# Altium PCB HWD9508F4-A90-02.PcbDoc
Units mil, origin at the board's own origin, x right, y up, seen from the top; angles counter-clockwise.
Board outline 3307.09 x 2401.57 mil, 2 copper layers (Top Layer, Bottom Layer); 56 components, 97 nets, 444 pads, 231 vias.
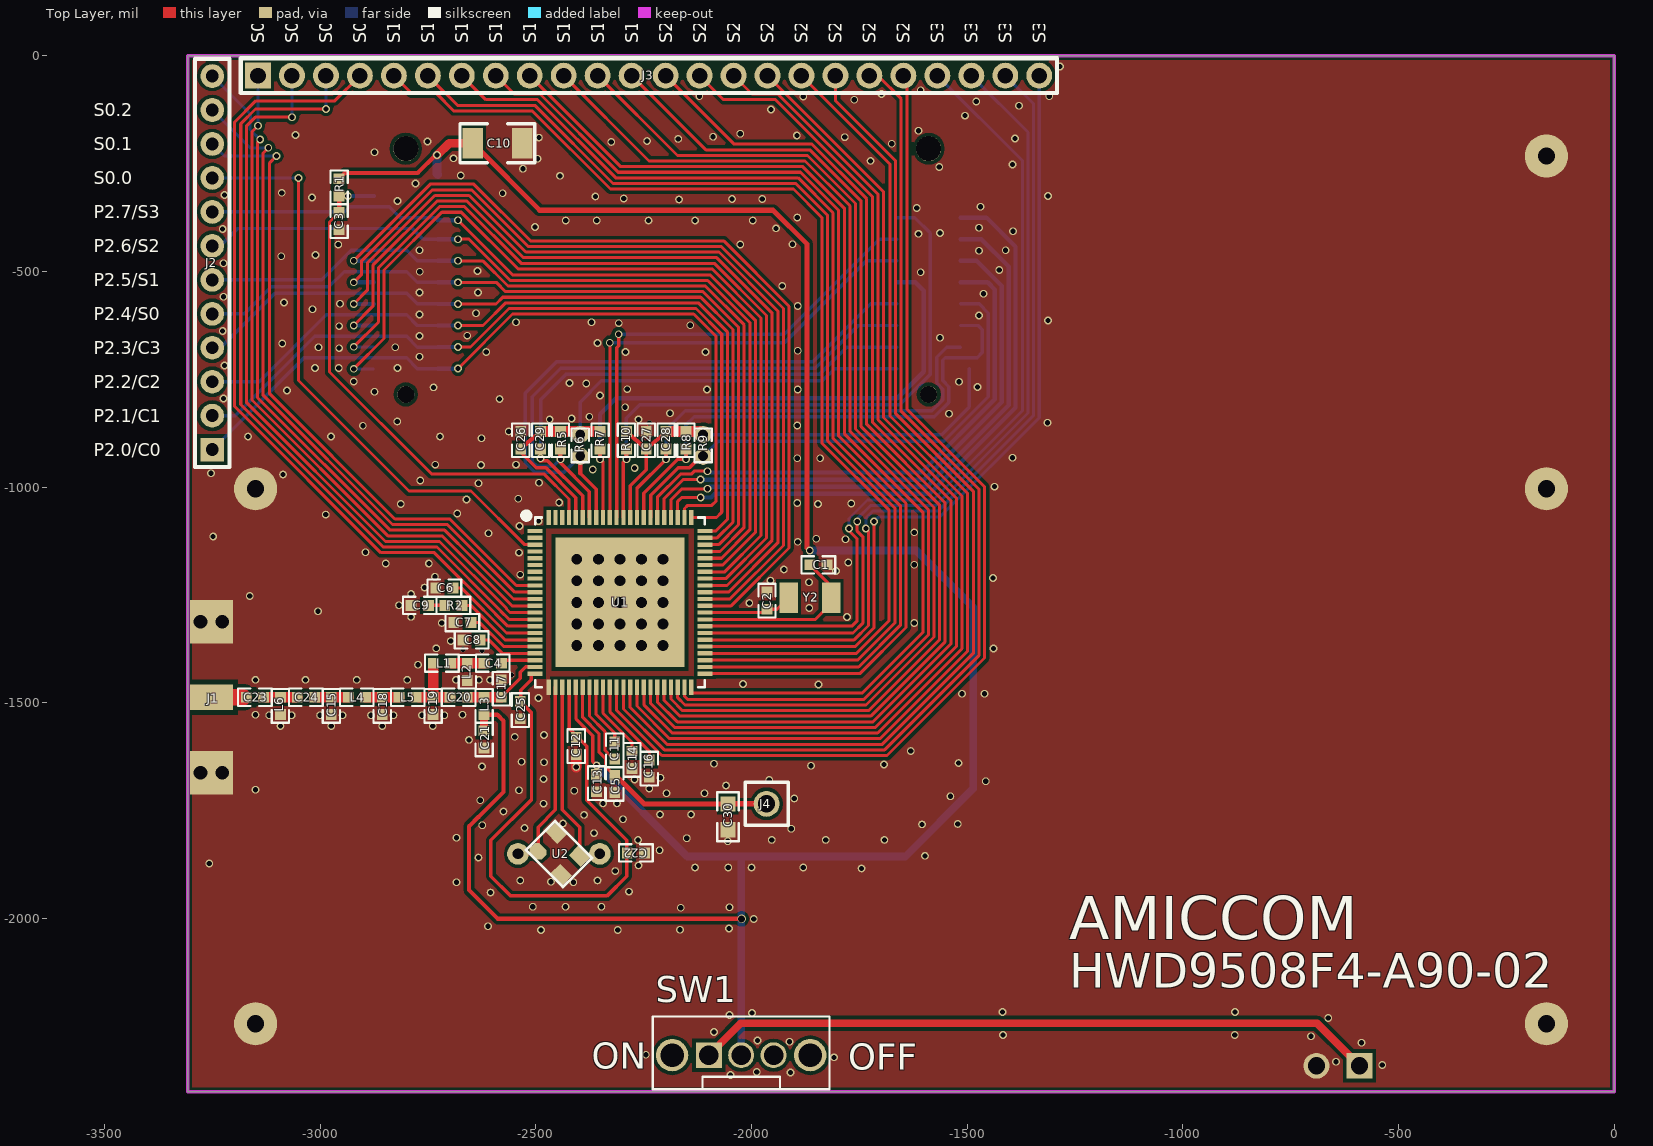
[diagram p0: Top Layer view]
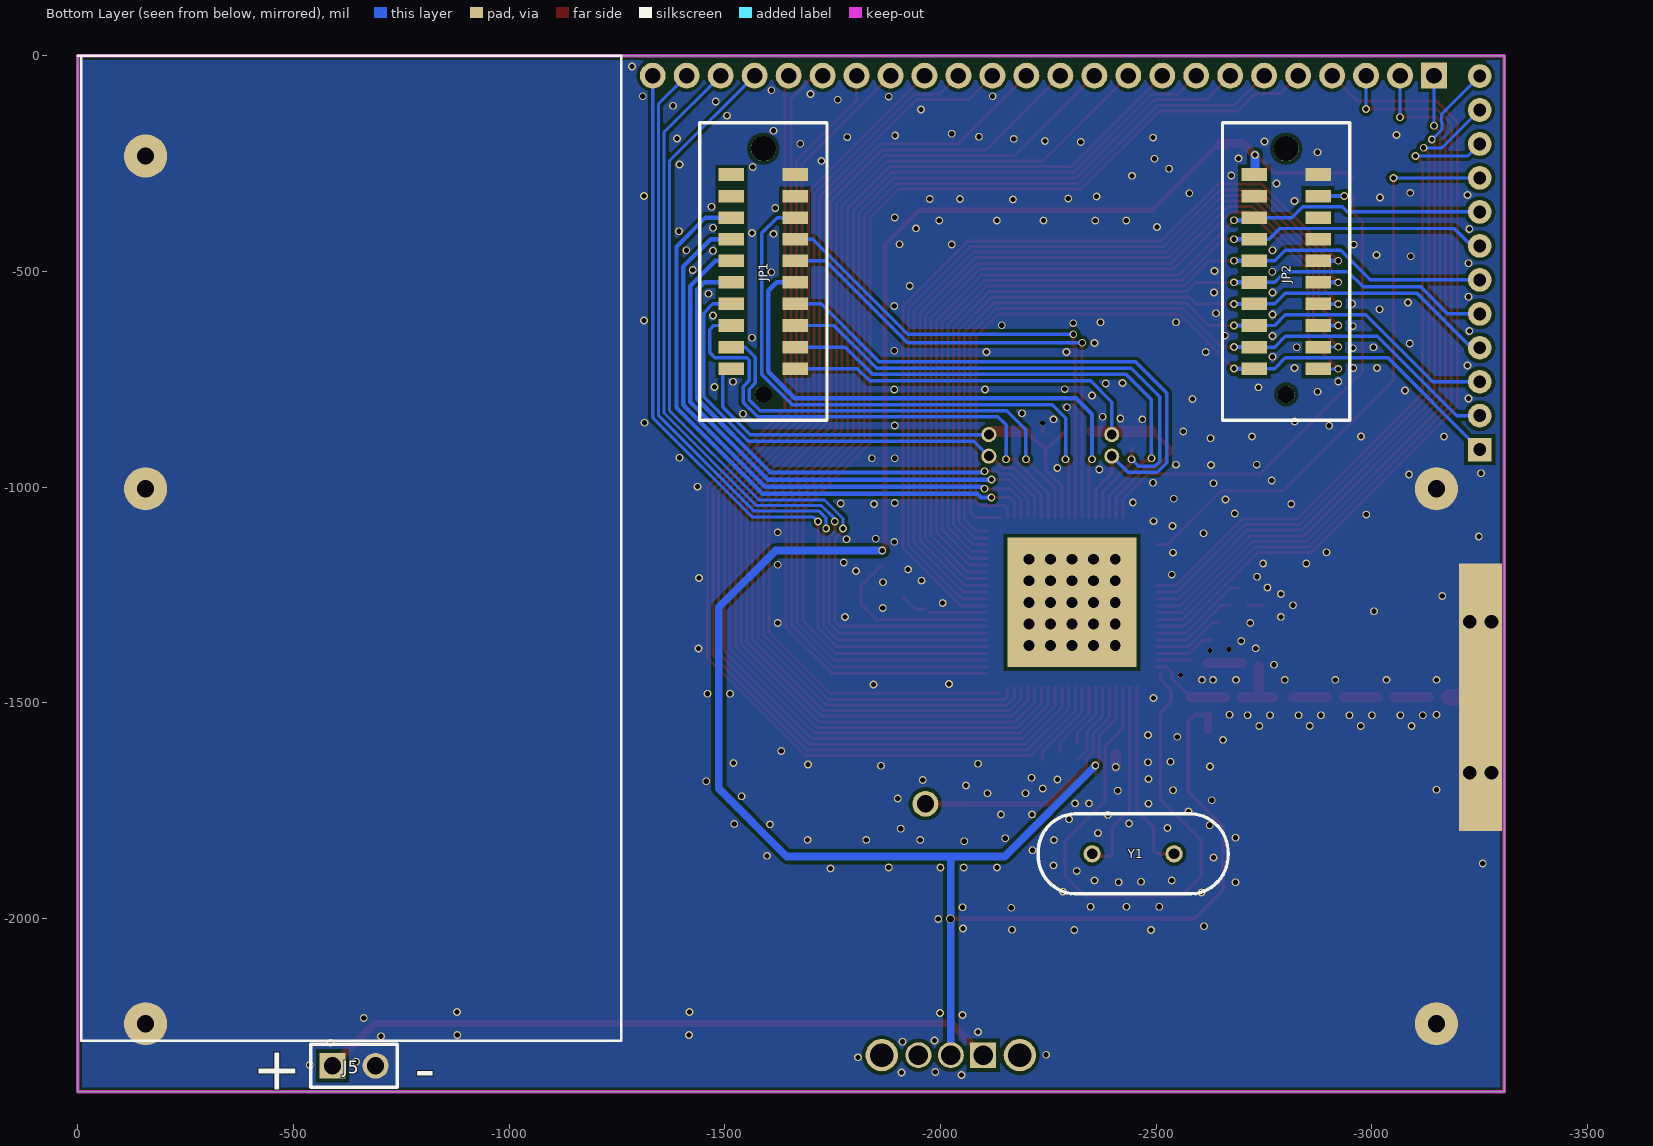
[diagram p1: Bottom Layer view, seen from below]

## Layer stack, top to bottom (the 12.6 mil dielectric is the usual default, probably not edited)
Top Solder: solder mask 0.4, Solder Resist, Dk 3.5
Top Layer: signal copper 1.4
Dielectric1: dielectric 12.6, FR-4, Dk 4.8
Bottom Layer: signal copper 1.4
Bottom Solder: solder mask 0.4, Solder Resist, Dk 3.5

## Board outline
-3307.09,-2401.57 -3307.09,0 0,0 0,-2401.57

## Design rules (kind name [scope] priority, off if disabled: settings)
Clearance Clearance_1 [All vs InNet('TRX')] p1: gap=12
Clearance [(InPoly) vs (IsWire) Or (IsPad) Or (IsVia) Or (IsFill) Or (InPoly)] p2: gap=8
Clearance Clearance_2 [All] p3: gap=6
ComponentClearance [All] p1 off: gap=10 collisioncheckmode=3 verticalgap=10 showdistances=FALSE
FabricationTestPointUsage TestPointUsage [All] p1: valid=0 allowmultiple=FALSE
FabricationTestpoint Testpoint [All] p1: side=3 testpointundercomponent=TRUE minsize=40 maxsize=100 preferedsize=60 minholesize=20 maxholesize=40 preferedholesize=32 testpointgrid=1 allowsidetop=TRUE allowsidebottom=TRUE usegrid=TRUE gridtolerance=0.01
HoleSize [All] p1: absolutevalues=TRUE maxlimit=200 minlimit=1 maxpercent=80.000 minpercent=20.000
PolygonConnect [All] p1: connectstyle=Direct reliefconductorwidth=10 reliefentries=4 polygonreliefangle="90 Angle" airgapwidth=10
RoutingLayers RoutingLayers_1 [InNet('RFIO')] p1: top layer_v5=TRUE bottom layer_v5=TRUE
RoutingLayers [All] p2: top layer_v5=TRUE bottom layer_v5=TRUE
RoutingVias [All] p1: holewidth=12 width=20 viastyle="Through Hole" minholewidth=12 minwidth=10 maxholewidth=16 maxwidth=20
ShortCircuit [All vs InNet('NetL2_1')] p1 off: allowed=FALSE
SolderMaskExpansion [HasPad('*A')] p1: expansion=-30
Width [All] p1: maxlimit=50 minlimit=7 preferedwidth=12
24 further rules are at their usual default settings.

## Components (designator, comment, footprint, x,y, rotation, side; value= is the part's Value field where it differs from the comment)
C1 "22p" 0402#1 -1865.09,-1180.24 r0 top
C2 "22p" 0402#1 -1964.09,-1283.24 r90 top
C3 "22nF" 0402#1 -2956.09,-363.43 r270 top
C4 "100pF" 0402#1 -2579.87,-1408.22 r180 top
C5 "2.2uF" 0402#1 -2317.09,-1668.24 r270 top
C6 "0.1uF" 0402#1 -2692.09,-1234.24 r180 top
C7 "1nF" 0402#1 -2650.09,-1314.24 r180 top
C8 "0.1uF" 0402#1 -2628.87,-1354.24 r180 top
C9 "0.1uF" 0402#1 -2749.09,-1274.24 r180 top
C10 "10uF" 1206 -2589,-203 r180 top (schematic designator C30)
C11 "47nF" 0402#1 -2317.09,-1630.44 r90 top
C12 "0.1uF" 0402#1 -2406.27,-1620.24 r90 top
C13 "2.2uF" 0402#1 -2359.09,-1666.24 r270 top
C14 "1uF" 0402#1 -2277.09,-1612.44 r270 top
C15 "4.7pF" 0402#1 -2974.09,-1527.24 r90 top
C16 "1uF" 0402#1 -2237.09,-1632.44 r270 top
C17 "NC" 0402#1 -2580.09,-1487.47 r90 top
C18 "4.7pF" 0402#1 -2856.09,-1527.24 r90 top
C19 "NC" 0402#1 -2738.09,-1487.24 r270 top
C20 "15pF" 0402#1 -2659.09,-1487.24 r180 top
C21 "2.2uF" 0402#1 -2620,-1565 r270 top
C22 "NC" 0402#1 -2248,-1848 r180 top
C23 "2.2pF" 0402#1 -3131.09,-1487.24 r180 top
C24 "2.2pF" 0402#1 -3013.09,-1487.24 r180 top
C25 "0.1uF" 0402#1 -2536,-1497 r270 top
C26 "820pF" 0402#1 -2535.09,-871.44 r270 top
C27 "NC" 0402#1 -2244.09,-871.44 r270 top
C28 "NC" 0402#1 -2198.09,-871.44 r270 top
C29 "820pF" 0402#1 -2489.09,-871.44 r270 top
C30 "NC" 0603 -2054.95,-1734.44 r270 top (schematic designator C31)
J1 "TRX" "SMA CONNECTOR" -3252.09,-1487.24 r90 top
J2 "CON/12P 2.0" HDR12_2.0 -3250.09,-913.31 r90 top
J3 "CON/24P 2.0" HDR24_2.0 -3144.09,-46.31 r0 top
J4 "LCDCAP_R33" HDR1_2.54 -1965.09,-1734.24 r0 top
J5 "BAT" HDR2_2.54 -590.55,-2341.58 r180 bottom
JP1 "HEADER 10X2B" YAB-V45P-2X#1 -1589.4,-785.27 r90 bottom locked
JP2 "HEADER 10X2B" YAB-V45P-2X#2 -2801.4,-785.27 r90 bottom locked
L1 "1.8pF" 0402#1 -2737.87,-1408.22 r0 top
L2 "8.2nH" 0402#1 -2658.87,-1408.22 r270 top
L3 "18nH" 0402#1 -2620.09,-1527.47 r90 top
L4 "7.5nH" 0402#1 -2935.09,-1487.24 r0 top
L5 "0R" 0402#1 -2817.09,-1487.24 r0 top
L6 "10nH" 0402#1 -3092.09,-1527.24 r90 top
R1 "100K" 0402#1 -2956.09,-285.43 r270 top
R2 "10R" 0402#1 -2711.09,-1274.24 r0 top
R5 "10K" 0402#1 -2443.09,-871.44 r270 top
R6 "thermistor,TSR" 0402#2 -2397.09,-883.44 r270 top
R7 "NC" 0402#1 -2351.09,-871.44 r270 top
R8 "NC" 0402#1 -2152.09,-871.44 r270 top
R9 "NC(thermistor,TSR)" 0402#2 -2112.09,-883.44 r270 top (schematic designator R6)
R10 "NC" 0402#1 -2290.09,-871.44 r270 top
SW1 "SW DIP-3P-180" SW3-2 -2099,-2317 r180 top
U1 "A9508F4_U01 PKG" "QFN 10*10 88L" -2304.95,-1267.36 r0 top
U2 "NC (12.8MHz, CL=20pF)" XTAL_3.2*2.5 -2446.68,-1850.24 r45 top locked
Y1 "12.8MHz, CL=20pF" XTAL1 -2446.66,-1850.22 r180 bottom
Y2 "32.768KHz" XTAL-XB -1904.09,-1256.24 r270 top

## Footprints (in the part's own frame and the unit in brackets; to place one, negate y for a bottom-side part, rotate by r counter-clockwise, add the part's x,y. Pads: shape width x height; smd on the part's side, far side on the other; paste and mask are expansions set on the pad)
0402#1 [mil]
  rect 25x25 smd: 1(0,0) 2(40,0)
  silkscreen extent -19,-20 59,20
0402#2 [mil]
  round 40 / inner round 35 / far side round 35 hole 23: 1(-5,0) 2(45,0)
  silkscreen extent -19,-20 59,20
0603 [mil]
  rect 35x35 smd: 1(0,0) 2(60,0)
  silkscreen extent -27,-25 87,25
1206 [mm]
  rect 1.2x1.8 smd: 1(1.45,0) 2(-1.45,0)
  silkscreen extent -2.21,-1.14 2.21,1.14
HDR1_2.54 [mil]
  round 60 hole 40: 1(0,0)
  silkscreen extent -50,-50 50,50
HDR2_2.54 [mil]
  rect 60x60 hole 40: 1(0,0)
  round 60 hole 40: 2(100,0)
  silkscreen extent -50,-50 150,50
HDR12_2.0 [mil]
  rect 55x55 hole 30: 1(0,0)
  round 55 hole 30: 2(78.74,0) 3(157.48,0) 4(236.22,0) 5(314.96,0) 6(393.7,0) 7(472.44,0) 8(551.18,0) 9(629.92,0) 10(708.66,0) 11(787.4,0) 12(866.14,0)
  silkscreen extent -40,-40 906,40
HDR24_2.0 [mil]
  rect 60x60 hole 36: 1(0,0)
  round 60 hole 36: 2(78.74,0) 3(157.48,0) 4(236.22,0) 5(314.96,0) 6(393.7,0) 7(472.44,0) 8(551.18,0) 9(629.92,0) 10(708.66,0) 11(787.4,0) 12(866.14,0) 13(944.88,0) 14(1023.62,0) 15(1102.36,0) 16(1181.1,0) 17(1259.84,0) 18(1338.58,0) 19(1417.32,0) 20(1496.06,0) 21(1574.8,0) 22(1653.54,0) 23(1732.28,0) 24(1811.02,0)
  silkscreen extent -40,-40 1852,40
"QFN 10*10 88L" [mm]
  rect 0.9x0.25 smd: 1(-5,4.2) 2(-5,3.8) 3(-5,3.4) 4(-5,3) 5(-5,2.6) 6(-5,2.2) 7(-5,1.8) 8(-5,1.4) 9(-5,1) 10(-5,0.6) 11(-5,0.2) 12(-5,-0.2) 13(-5,-0.6) 14(-5,-1) 15(-5,-1.4) 16(-5,-1.8) 17(-5,-2.2) 18(-5,-2.6) 19(-5,-3) 20(-5,-3.4) 21(-5,-3.8) 22(-5,-4.2) 45(5,-4.2) 46(5,-3.8) 47(5,-3.4) 48(5,-3) 49(5,-2.6) 50(5,-2.2) 51(5,-1.8) 52(5,-1.4) 53(5,-1) 54(5,-0.6) 55(5,-0.2) 56(5,0.2) 57(5,0.6) 58(5,1) 59(5,1.4) 60(5,1.8) 61(5,2.2) 62(5,2.6) 63(5,3) 64(5,3.4) 65(5,3.8) 66(5,4.2)
  rect 0.25x0.9 smd: 23(-4.2,-5) 24(-3.8,-5) 25(-3.4,-5) 26(-3,-5) 27(-2.6,-5) 28(-2.2,-5) 29(-1.8,-5) 30(-1.4,-5) 31(-1,-5) 32(-0.6,-5) 33(-0.2,-5) 34(0.2,-5) 35(0.6,-5) 36(1,-5) 37(1.4,-5) 38(1.8,-5) 39(2.2,-5) 40(2.6,-5) 41(3,-5) 42(3.4,-5) 43(3.8,-5) 44(4.2,-5) 67(4.2,5) 68(3.8,5) 69(3.4,5) 70(3,5) 71(2.6,5) 72(2.2,5) 73(1.8,5) 74(1.4,5) 75(1,5) 76(0.6,5) 77(0.2,5) 78(-0.2,5) 79(-0.6,5) 80(-1,5) 81(-1.4,5) 82(-1.8,5) 83(-2.2,5) 84(-2.6,5) 85(-3,5) 86(-3.4,5) 87(-3.8,5) 88(-4.2,5)
  round 0.635 hole 0.635: ""(-2.54,-2.54) ""(-2.54,-1.27) ""(-2.54,0) ""(-2.54,1.27) ""(-2.54,2.54) ""(-1.27,-2.54) ""(-1.27,-1.27) ""(-1.27,0) ""(-1.27,1.27) ""(0,-2.54) ""(0,-1.27) ""(0,1.27) ""(0,2.54) ""(1.27,-2.54) ""(1.27,-1.27) ""(1.27,0) ""(1.27,1.27) ""(1.27,2.54) ""(2.54,-2.54) ""(2.54,-1.27) ""(2.54,0) ""(2.54,1.27) ""(2.54,2.54)
  round 0.762 hole 0.635: ""(-1.27,2.54)
  rect 7.62x7.62 hole 0.635: ""(0,0)
  silkscreen extent -5.62,-5 5,5.21
"SMA CONNECTOR" [mil]
  rect 100x50 hole 32: 0(-175,-25) 0(-175,25) 0(175,-25) 0(175,25)
  rect 620x100 smd far side: 0(0,0)
  rect 59.05x100 smd: 1(0,0)
SW3-2 [mil]
  rect 60x60 hole 45: 1(0,0)
  round 60 hole 45: 2(-75,0) 3(-150,0)
  round 75 hole 55: ""(-235,0) ""(85,0)
  silkscreen extent -280,-90 130,79
XTAL1 [mil]
  round 40 / inner round 40 / far side round 50 hole 25: 1(-95,0) 2(95,0)
  silkscreen extent -220,-93 220,93
XTAL-XB [mm]
  rect 1.8x1.1 smd: 1(0,-0.25) 2(0,2.25)
XTAL_3.2*2.5 [mm]
  oct 0.8x1 smd: 1(-0.76,0.97)
  rect 0.8x1 smd: 2(-0.76,-0.97) 3(0.76,-0.97) 4(0.75,0.97)
  silkscreen extent -1.21,-1.55 1.22,1.53
YAB-V45P-2X#1 [mm]
  rect 0.74x1.5 smd: 1(1.52,1.875) 2(2.79,1.875) 3(4.06,1.875) 4(5.33,1.875) 5(6.6,1.875) 6(7.87,1.875) 7(9.14,1.875) 8(10.41,1.875) 9(11.68,1.875) 10(12.95,1.875) 11(1.52,-1.875) 12(2.79,-1.875) 13(4.06,-1.875) 14(5.33,-1.875) 15(6.6,-1.875) 16(7.87,-1.875) 17(9.14,-1.875) 18(10.41,-1.875) 19(11.68,-1.875) 20(12.95,-1.875)
  round 1 hole 1 unplated: ""(0,0)
  round 1.473 hole 1.473 unplated: ""(14.47,0)
  silkscreen extent -1.52,-3.75 15.98,3.75
YAB-V45P-2X#2 [mm]
  rect 0.74x1.5 smd: 1(1.52,1.875) 2(2.79,1.875) 3(4.06,1.875) 4(5.33,1.875) 6(7.87,1.875) 7(9.14,1.875) 8(10.41,1.875) 9(11.68,1.875) 10(12.95,1.875) 11(1.52,-1.875) 12(2.79,-1.875) 13(4.06,-1.875) 14(5.33,-1.875) 15(6.6,-1.875) 16(7.87,-1.875) 17(9.14,-1.875) 18(10.41,-1.875) 19(11.68,-1.875) 20(12.95,-1.875)
  rect 0.76x1.5 smd: 5(6.6,1.875)
  round 1 hole 1 unplated: ""(0,0)
  round 1.473 hole 1.473 unplated: ""(14.47,0)
  silkscreen extent -1.52,-3.75 15.98,3.75

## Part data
C1 C2 C11: library part C/0603, "Chip C"
C3 C26 C27 C28 C29: library part C/0402, "Chip C"
C4 C5 C6 C7 C8 C9 C10 C12 C13 C14 C15 C16 C17 C18 C19 C20 C21 C22 C23 C24 C25 C30: library part CAP
J1: library part "SMA CONNECTOR"
J2 J3: "Hole 36mil"
J4: library part "CON/1P 2.54", "Hole 40mil"
J5: library part "CON/2P 2.54", "Hole 40mil"
JP1 JP2: "Pitch 2.54mm"
L1 L2 L3 L4 L5 L6: library part L/0402, "Chip L"
R1: library part R/0603, "Chip  R"
R2: library part RES1
R5 R6 R7 R8 R9 R10: library part R/0402, "Chip R"
U1: library part A9508F4
U2: library part CRYSTAL/5*3.2
Y1 Y2: library part CRYSTAL, "Crystal"

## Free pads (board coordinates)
  round 18 hole 12: A(-3167.09,-882.87) A(-3150.09,-1527.87) A(-3150.09,-1446.87) A(-3118.09,-1528.87) A(-3092.09,-1553.87) A(-3086.09,-970.87) A(-3066.09,-1528.87) A(-3034.09,-1446.87) A(-3005,-1288) A(-3000.09,-1528.87) A(-2987.09,-1063.87) A(-2974.09,-1553.87) A(-2958,-438) A(-2948.09,-1528.87) A(-2915.09,-1446.87) A(-2895,-1151) A(-2882.09,-1528.87) A(-2874.09,-779.24) A(-2856.09,-1553.87) A(-2830.09,-1528.87) A(-2821.09,-847.87) A(-2817.09,-1273.87) A(-2798.09,-1446.87) A(-2789.09,-1300.87) A(-2789.09,-1247.87) A(-2773.09,-1411.87) A(-2764.09,-1528.87) A(-2758.09,-1232.87) A(-2739.09,-1553.87) A(-2737.09,-768.87) A(-2734.09,-1207.87) A(-2731.09,-1373.87) A(-2722.09,-882.87) A(-2718.09,-1314.87) A(-2712.09,-1528.87) A(-2697.09,-1356.87) A(-2685.09,-1446.87) A(-2670.09,-1527.87) A(-2655,-1586) A(-2633.09,-1858.87) A(-2632.09,-1446.87) A(-2626.09,-886.87) A(-2624.09,-1783.87) A(-2615,-687) A(-2606.09,-1446.87) A(-2605.09,-1939.87) A(-2584.09,-795.87) A(-2575.09,-1751.87) A(-2562.8,-871.07) A(-2546,-618) A(-2539.09,-1702.87) A(-2536.24,-1911.87) A(-2533.09,-1636.87) A(-2530.09,-262.24) A(-2526.09,-1790.24) A(-2507.09,-1972.87) A(-2496,-239) A(-2493,-190) A(-2482.09,-1733.87) A(-2482.09,-1676.87) A(-2481,-1638) A(-2465.09,-1914.87) A(-2437.09,-1779.87) A(-2431.09,-1972.87) A(-2430.8,-382.24) A(-2413.09,-1915.87) A(-2411.09,-1703.87) A(-2406.27,-1648.87) A(-2388.09,-1759.87) A(-2371,-618) A(-2365.09,-1802.24) A(-2362.09,-326.24) A(-2358.8,-382.24) A(-2357.09,-1911.87) A(-2348.09,-1972.87) A(-2344.09,-1733.24) A(-2325.09,-199.87) A(-2316.09,-1890.24) A(-2312.09,-1733.24) A(-2298.09,-1769.87) A(-2296.09,-331.24) A(-2284.09,-1937.87) A(-2271.09,-1677.87) A(-2263,-1818) A(-2262,-1877) A(-2242.09,-197.87) A(-2238.8,-382.24) A(-2237.09,-1698.87) A(-2213.09,-1841.87) A(-2212.09,-1758.87) A(-2211.09,-1673.87) A(-2197.09,-1709.87) A(-2170.09,-192.87) A(-2168.09,-333.24) A(-2150.09,-1813.87) A(-2140.09,-1758.87) A(-2131,-1882) A(-2130.8,-382.24) A(-2109.09,-1709.87) A(-2089.09,-187.87) A(-2087.09,-1641.36) A(-2059.09,-1691.87) A(-2055.09,-1820.87) A(-2054,-1882) A(-2045.09,-332.24) A(-2026.09,-180.87) A(-2005.09,-1268.87) A(-2000,-1882) A(-1997.09,-382.24) A(-1975.09,-332.24) A(-1959.09,-1678.87) A(-1956.09,-1216.87) A(-1953.09,-1817.87) A(-1943.09,-400.24) A(-1925.09,-1190.87) A(-1908.09,-1791.87) A(-1905.09,-437.29) A(-1901.09,-1721.87) A(-1894.09,-375.24) A(-1862.09,-1645.87) A(-1828.09,-1817.87) A(-1784.09,-188.87) A(-1745,-1884) A(-1724.09,-243.87) A(-1692.09,-1817.87) A(-1631,-1612) A(-1604.8,-1781.87) A(-1598.09,-1854.87) A(-1539.09,-1716.87) A(-1522.09,-1780.87) A(-1520.09,-1639.87) A(-1457.09,-1681.87)
  round 12 hole 12: A(-2669.09,-1375.87) A(-2625.09,-1378.87) A(-2556.09,-1435.87) A(-2237.09,-851.44)
  round 100 hole 40: ""(-3149.61,-2244.09) ""(-3149.61,-1003.94) ""(-157.48,-2244.09) ""(-157.48,-1003.94) ""(-157.48,-232.61)

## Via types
v1: diameter 18, hole 12, Top Layer to Bottom Layer, 204 vias
v2: diameter 18, hole 12, Top Layer to Bottom Layer, tented both sides, 26 vias
v3: diameter 20, hole 16, Top Layer to Bottom Layer, 1 vias

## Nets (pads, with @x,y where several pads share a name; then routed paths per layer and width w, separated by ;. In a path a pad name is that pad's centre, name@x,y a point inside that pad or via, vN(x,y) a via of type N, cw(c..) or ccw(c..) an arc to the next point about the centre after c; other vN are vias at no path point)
BPBG: C7.1 U1.18 | length 164.3
  Top Layer w7: C7.1@-2643.09,-1314.24 -2630.09,-1314.24 -2574.61,-1369.72 U1.18
CPO: C16.1 U1.32 | length 206.1
  Top Layer w7: U1.32 -2328.57,-1520.76 -2237.09,-1612.24 C16.1
GND: C1.2 C2.2 C3.2 C5.2 C6.2 C7.2 C8.2 C9.2 C10.2 C12.1 C13.2 C14.2 C15.1 C16.2 C17.2 C18.1 C19.2 C21.2 C22.1 C25.2 C26.1 C27.1 C30.2 J1.0 J5.2 JP1.20 JP2.20 L2.2 L6.1 pad. pad.A U1.23 U2.2 U2.4 | length 48.6
  Top Layer w10: C27.1@-2237.09,-871.44 pad.A@-2237.09,-851.44
  Top Layer w25: pad.A@-2406.27,-1648.87 C12.1
  other v1: -2049,-2363 -1910,-2357 -1988,-2356 -538,-2340 -645,-2332 -1809,-2322 -2245,-2316 -586,-2288 -1912,-2286 -1986,-2283 -703,-2273 -1417,-2270 -880,-2270 -2087,-2263 -663,-2231 -2051,-2224 -1999,-2219 -1418,-2217 -879,-2217 -2488,-2027 -2310,-2027 -2166,-2026 -2052,-2023 -2611,-2018 -1995,-2001 -2164,-1975 -2051,-1974 -2684,-1916 -1880,-1882 -3257.09,-1872.58 -2684,-1813 -2629,-1726 -3150.09,-1701.58 -2625,-1648 -1693,-1643 -2549,-1579 -2481,-1575 -2494,-1489 -1512,-1479 -1460,-1479 -1845.09,-1457.58 -2020.09,-1456.58 -1439,-1374 -1623,-1315 -1779,-1301 -1866.09,-1280.58 -3163.09,-1252.58 -1867.09,-1220.58 -1440,-1211 -2536,-1203 -1804.09,-1194.58 -1623,-1180 -2848,-1177 -2748,-1177 -1776,-1175 -2539,-1152 -1893,-1127 -1782,-1121 -1850,-1120 -3248.09,-1114.58 -2610,-1107 -1623,-1105 -2538,-1090 -2494,-1079 -2682,-1061 -2813,-1039 -1846,-1039 -1769,-1038 -1894,-1037 -2446,-1036 -2661,-1029 -2541,-1027 -1437,-999 -2633,-991 -2493,-990 -2768,-985 -3253,-968 -2368,-959 -2271,-956 -2627,-949 -2733,-948 -2546,-948 -1894,-933 -1841,-933 -1395,-932 -2975,-883 -2901,-858 -1894,-857 -1314,-851 -2468,-843 -2262,-843 -2417,-841 -2376,-837 -1542,-830 -2189,-829 -2293,-815 -3224,-795 -2351,-788 -3077,-776 -2103,-774 -1893,-774 -2288,-773 -1476,-768 -2383,-760 -2422,-759 -1519,-756 -2922,-755 -3012,-724 -2957,-724 -2821,-724 -3222,-718 -2770,-698 -2292,-687 -2107,-687 -1893,-684 -2956,-678 -3004,-676 -2826,-676 -3088,-667 -2357,-666 -1563,-654 -2770,-650 -2659,-649 -3226,-638 -2956,-627 -2142,-625 -2308,-620 -1313,-614 -1473,-602 -2770,-600 -2639,-597 -3018,-588 -1893,-580 -2954,-575 -3084,-572 -3224,-559 -1462,-552 -2770,-549 -2634,-549 -1929,-534 -1608,-502 -2769,-501 -2635,-499 -1426,-497 -3224,-481 -3090,-465 -3011,-462 -1473,-452 -2770,-451 -1411,-451 -2026,-438 -1613,-413 -1563,-411 -1394,-407 -3226,-402 -1473,-399 -2502,-397 -1617,-353 -1469,-350 -2821,-337 -3019,-329 -1313,-325 -3222,-323 -2577,-319 -3089,-318 -2779,-296 -2674,-278 -2444.09,-278.58 -1565,-258 -1395,-252 -2691,-238 -2874,-224 -1675,-204 -2751,-199 -1389,-192 -1895,-185 -3057,-184 -1613,-174 -1505,-139 -1955,-125 -1380,-116 -1479,-106 -1762,-102 -1880,-95 -2121,-94 -1310,-94 -1699,-89 -1608,-80 -1285,-25
LCDCAP_R33: C5.1 C30.1 J4.1 U1.28 | length 614.6
  Top Layer w7: U1.28 -2391.56,-1533.77 -2354.09,-1571.24 -2354.09,-1613.87 -2339.09,-1628.87 -2339.09,-1646.87 C5.1@-2314.09,-1671.87 ; C5.1@-2314.09,-1672.24 C5.1@-2311.09,-1672.24
  Top Layer w12: C5.1@-2311.09,-1672.24 -2248.89,-1734.44 C30.1 -2054.75,-1734.24 J4.1
NetC4_2: C4.2 L1.2 L2.1 | length 78
  Top Layer w25: L1.2 L2.1 C4.2
NetC9_1: C9.1 R2.1 | length 38
  Top Layer w8: C9.1 R2.1
NetC11_1: C11.1 U1.29 | length 192.6
  Top Layer w7: U1.29 -2375.81,-1530.52 -2340.09,-1566.24 -2340.09,-1609.44 C11.1@-2317.09,-1632.44
NetC11_2: C11.2 U1.30 | length 146
  Top Layer w7: U1.30 -2360.06,-1527.27 -2317.09,-1570.24 C11.2@-2317.09,-1592.44
NetC15_2: C15.2 C24.1 L4.1 | length 78
  Top Layer w25: C24.1 C15.2 L4.1
NetC18_2: C18.2 L4.2 L5.1 | length 78
  Top Layer w25: L4.2 C18.2 L5.1
NetC19_1: C19.1 C20.2 L1.1 L5.2 | length 134.2
  Top Layer w25: L5.2@-2770.09,-1487.22 -2731.09,-1487.22 C20.2 ; C19.1@-2737.87,-1480.44 L1.1@-2737.87,-1417.24
NetC23_1: C23.1 C24.2 L6.2 | length 78
  Top Layer w25: C23.1 L6.2 C24.2
NetJ5_1: J5.1 SW1.1 | length 1579.9
  Top Layer w18: SW1.1 -2025,-2243 -689.13,-2243 J5.1
P0.0: C26.2 C29.1 JP1.11 R5.1 R6.1 R7.1 U1.84 | length 1267.7
  Top Layer w8: C26.2 -2535.09,-919.44 -2499.28,-955.24 -2476.55,-955.24 -2407.31,-1024.49 U1.84
  Top Layer w10: C26.2 C29.1 C29.1@-2491.09,-871.44
  Top Layer w25: C29.1 R5.1 -2397.09,-871.44 R7.1
  Bottom Layer w8: R6.1 -2397.09,-803.09 -2348,-754 -1836,-754 -1807.43,-725.43 JP1.11
P0.1: C29.2 JP1.12 U1.83 | length 1221.1
  Top Layer w8: v1@-2489.09,-939 -2473,-939 -2391.56,-1020.44 U1.83
  Top Layer w10: v1@-2489.09,-939 C29.2
  Bottom Layer w8: v1(-2489.09,-933) -2489.09,-797.09 -2431,-739 -1843,-739 -1779.43,-675.43 JP1.12
P0.2: JP1.13 R5.2 U1.82 | length 1326.9
  Top Layer w8: v1(-2443.09,-935.44) -2443.09,-943.13 -2375.81,-1010.4 U1.82
  Top Layer w10: v1(-2443.09,-935.44) R5.2
  Bottom Layer w8: v1(-2443.09,-935.44) -2459.65,-952 -2496.96,-952 -2508.09,-940.87 -2508.09,-790.61 -2442.47,-725 -1852,-725 -1752.43,-625.43 JP1.13
P0.3: JP1.14 R6.2 U1.81 | length 1419.2
  Top Layer w8: -2397.09,-967.91 -2360.06,-1004.94 U1.81
  Top Layer w10: -2397.09,-967.91 R6.2
  Bottom Layer w8: R6.2 -2434.65,-966 -2502.76,-966 -2525,-943.76 -2525,-782 -2453,-710 -1858,-710 -1723.43,-575.43 JP1.14
P0.4/DEBUG_EN_EK: JP1.15 R7.2 U1.80 | length 1315.1
  Top Layer w8: v1(-2351.09,-935.44) -2344.32,-942.21 U1.80
  Top Layer w10: v1(-2351.09,-935.44) R7.2
  Bottom Layer w10: v1(-2351.09,-935.44) -2351.09,-831.09 -2314,-794 -1662.21,-794 -1601,-732.79 -1601,-545 -1620.57,-525.43 JP1.15
P0.5: JP1.16 U1.79 | length 1149
  Top Layer w7: U1.79 v2(-2328.57,-665.61)
  Bottom Layer w8: v2(-2328.57,-665.61) -1923.61,-665.61 -1733.43,-475.43 JP1.16
P0.6: JP1.17 U1.78 | length 1162.9
  Top Layer w8: U1.78 -2312.82,-676.74 -2308.09,-672 v2(-2308.09,-645.61)
  Bottom Layer w8: v2(-2308.09,-645.61) -1924.61,-645.61 -1704.43,-425.43 JP1.17
P0.7/GIO1: JP1.18 R10.2 U1.77 | length 1423.2
  Top Layer w8: U1.77 -2297.07,-942.43 v1(-2290.09,-935.44)
  Top Layer w10: v1(-2290.09,-935.44) R10.2
  Bottom Layer w8: v1(-2290.09,-935.44) -2290.09,-840.09 -2259,-809 -1656,-809 -1586,-739 -1586,-411 -1621.57,-375.43 JP1.18
P1.0: C27.2 C28.1 JP1.1 R8.1 R9.1 R10.1 U1.76 | length 1117.8
  Top Layer w8: U1.76 -2281.32,-997.32 -2244.09,-960.09 C27.2
  Top Layer w10: R10.1@-2289.09,-871.44 R10.1 C27.2 -2197.27,-872.42 C28.1@-2196.09,-871.44
  Top Layer w25: C28.1@-2196.09,-871.44 R8.1 -2119.09,-871.44 R9.1
  Bottom Layer w8: R9.1 -1559.08,-878.44 -1495,-814.36 JP1.1@-1495,-726
P1.1: C28.2 JP1.2 U1.75 | length 1095.2
  Top Layer w8: U1.75 -2265.58,-1002.93 v1(-2198.09,-935.44)
  Top Layer w10: v1(-2198.09,-935.44) C28.2
  Bottom Layer w8: v1(-2198.09,-935.44) -2198.09,-867.09 -2154,-823 -1581.8,-823 -1557,-798.2 -1557,-772.8 -1571,-758.8 -1571,-699 -1547.43,-675.43 JP1.2
P1.2/GIO2: JP1.3 R8.2 U1.74 | length 1231.6
  Top Layer w8: U1.74 -2249.83,-1014.05 -2171.22,-935.44 v1(-2152.09,-935.44)
  Top Layer w10: v1(-2152.09,-935.44) R8.2
  Bottom Layer w8: v1(-2152.09,-935.44) -2152.09,-856.09 -2133,-837 -1576,-837 -1543,-804 -1543,-767 -1557,-753 -1557,-706 -1551,-700 -1477,-700 -1465,-688 -1465,-635 -1474.57,-625.43 JP1.3
P1.3/CKO_EK: JP1.4 R9.2 U1.73 | length 1206
  Top Layer w8: U1.73 -2234.08,-1019.24 -2170.09,-955.24 -2143.89,-955.24 -2124.09,-935.44 R9.2@-2106.09,-935.44
  Top Layer w10: R9.2@-2106.09,-935.44 R9.2@-2106.09,-928.44
  Bottom Layer w8: R9.2 -2077.65,-894 -1554.84,-894 -1451,-790.16 -1451,-597 -1472.57,-575.43 JP1.4
P1.4/TTDIO: JP1.5 U1.72 | length 1266.7
  Top Layer w7: U1.72 -2218.33,-1023.49 -2164.84,-970 -2139.55,-970 -2132.8,-963.24 v2(-2102.09,-963.24)
  Bottom Layer w10: v2(-2102.09,-963.24) -2099.09,-966.24 -1605.87,-966.24 -1436,-796.37 -1436,-542 -1452.57,-525.43 JP1.5
P1.5/TTCLK: JP1.6 U1.71 | length 1308.7
  Top Layer w7: U1.71 -2202.58,-1026.74 -2158.84,-983 -2118.84,-983 v2(-2118.09,-982.24)
  Bottom Layer w10: v2(-2118.09,-982.24) -2117.09,-983.24 -1600.24,-983.24 -1420,-803 -1420,-534 -1478.57,-475.43 JP1.6
P1.6: JP1.7 U1.70 | length 1373.5
  Top Layer w7: U1.70 -2186.84,-1029.38 -2161.46,-1004 v1(-2102,-1004)
  Bottom Layer w10: v1(-2102,-1004) -2097.24,-999.24 -1593.62,-999.24 -1404,-809.63 -1404,-489 -1467.57,-425.43 JP1.7
P1.7: JP1.8 U1.69 | length 1439.2
  Top Layer w7: U1.69 -2171.09,-1033.09 -2162,-1024 v1(-2118,-1024)
  Bottom Layer w10: v1(-2118,-1024) -2093.72,-1024 -2084.96,-1015.24 -1586.99,-1015.24 -1388,-816.25 -1388,-443 -1455.57,-375.43 JP1.8
P2.0/C0: J2.1 JP2.1 U1.68 | length 1823
  Top Layer w7: v2(-2680.54,-725.43) -2554.1,-599 -2134,-599 -2082.09,-650.91 -2082.09,-1032.24 -2093.09,-1043.24 -2149.09,-1043.24 -2155.34,-1049.5 U1.68
  Bottom Layer w8: J2.1 -3037.39,-700.61 -2799.45,-700.61 -2774.63,-725.43 JP2.1
  Bottom Layer w10: JP2.1 v2(-2680.54,-725.43)
P2.1/C1: J2.2 JP2.2 U1.67 | length 1798.5
  Top Layer w7: v2(-2680.54,-675.43) -2651.43,-675.43 -2562,-586 -2128.62,-586 -2069.09,-645.53 -2069.09,-1058.24 -2081.35,-1070.51 U1.67
  Bottom Layer w8: J2.2@-3231.09,-834.58 -3196.58,-834.58 -3012.61,-650.61 -2799.45,-650.61 -2774.63,-675.43 JP2.2
  Bottom Layer w10: JP2.2 v2(-2680.54,-675.43)
P2.2/C2: J2.3 JP2.3 U1.66 | length 1797.3
  Top Layer w7: v2(-2680.54,-625.43) -2622.43,-625.43 -2570,-573 -2123.23,-573 -2056.09,-640.15 -2056.09,-1075.26 -2082.84,-1102.01 U1.66
  Bottom Layer w8: J2.3@-3231.09,-755.84 -3140.83,-755.84 -2985.61,-600.61 -2799.45,-600.61 -2774.63,-625.43 JP2.3
  Bottom Layer w10: JP2.3 v2(-2680.54,-625.43)
P2.3/C3: J2.4 JP2.4 U1.65 | length 1814.6
  Top Layer w7: v2(-2680.54,-575.43) -2592.43,-575.43 -2577,-560 -2117.85,-560 -2043.09,-634.76 -2043.09,-1081.24 -2079.6,-1117.76 U1.65
  Bottom Layer w8: J2.4@-3231.09,-677.09 -3104.61,-550.61 -2799.45,-550.61 -2774.63,-575.43 JP2.4
  Bottom Layer w10: JP2.4 v2(-2680.54,-575.43)
P2.4/S0: J2.5 JP2.5 U1.64 | length 1849.9
  Top Layer w7: v2(-2680.54,-525.43) -2591.69,-525.43 -2570.12,-547 -2112.46,-547 -2030.09,-629.38 -2030.09,-1087.24 -2076.35,-1133.5 U1.64
  Bottom Layer w8: J2.5@-3231.09,-598.35 -3175.35,-598.35 -3113,-536 -2980,-536 -2944.61,-500.61 -2799.45,-500.61 -2774.63,-525.43 JP2.5
  Bottom Layer w10: JP2.5 v2(-2680.54,-525.43)
P2.5/S1: J2.6 JP2.6 U1.63 | length 1897.9
  Top Layer w7: v2(-2680.54,-475.43) -2623.31,-475.43 -2564.74,-534 -2107.08,-534 -2017.09,-623.99 -2017.09,-1093.24 -2073.09,-1149.25 U1.63
  Bottom Layer w8: J2.6@-3231.09,-519.61 -2996.61,-519.61 -2927.61,-450.61 -2799.45,-450.61 -2774.63,-475.43 JP2.6
  Bottom Layer w10: JP2.6 v2(-2680.54,-475.43)
P2.6/S2: J2.7 JP2.7 U1.62 | length 1945.9
  Top Layer w7: v2(-2680.54,-425.43) -2654.92,-425.43 -2559.36,-521 -2101.69,-521 -2004.09,-618.61 -2004.09,-1099.24 -2069.84,-1165 U1.62
  Bottom Layer w8: J2.7@-3231.09,-440.87 -3190.83,-400.61 -2786.39,-400.61 -2761.57,-425.43 JP2.7
  Bottom Layer w10: JP2.7 v2(-2680.54,-425.43)
P2.7/S3: J2.8 JP2.8 U1.61 | length 1991.4
  Top Layer w7: v2(-2680.54,-381.43) -2553.97,-508 -2096.31,-508 -1991.09,-613.22 -1991.09,-1105.24 -2066.59,-1180.75 U1.61
  Bottom Layer w8: J2.8@-3231.09,-362.13 -2943.13,-362.13 -2931.61,-350.61 -2839.39,-350.61 -2814.57,-375.43 JP2.8
  Bottom Layer w10: JP2.8@-2727.58,-381.43 v2(-2680.54,-381.43)
P3.0: JP2.11 U1.60 | length 2004.5
  Top Layer w7: v1(-2922,-726) -2851.77,-655.77 -2851.77,-496.77 -2717.93,-362.93 -2672.87,-362.93 -2541.56,-494.24 -2091.68,-494.24 -1978.09,-607.84 -1978.09,-1112.47 -2062.11,-1196.5 U1.60
  Bottom Layer w7: v1(-2922,-726) JP2.11@-2875.79,-726
P3.1: JP2.12 U1.59 | length 2014.1
  Top Layer w7: v1(-2922,-675) -2864.77,-617.77 -2864.77,-491.38 -2723.32,-349.93 -2665.37,-349.93 -2534.06,-481.24 -2086.29,-481.24 -1965.09,-602.45 -1965.09,-1117.86 -2059.47,-1212.24 U1.59
  Bottom Layer w7: v1(-2922,-675) JP2.12@-2875.65,-675
P3.2: JP2.13 U1.58 | length 2025.7
  Top Layer w7: v2(-2922.27,-625.43) -2877.77,-580.93 -2877.77,-486 -2728.7,-336.93 -2659.99,-336.93 -2528.68,-468.24 -2080.91,-468.24 -1952.09,-597.07 -1952.09,-1123.24 -2056.83,-1227.99 U1.58
  Bottom Layer w10: v2(-2922.27,-625.43) JP2.13
P3.3: JP2.14 U1.57 | length 2036.4
  Top Layer w7: v2(-2922.27,-575.43) -2890.77,-543.93 -2890.77,-480.61 -2734.09,-323.93 -2654.6,-323.93 -2523.29,-455.24 -2075.53,-455.24 -1939.09,-591.68 -1939.09,-1129.24 -2053.58,-1243.74 U1.57
  Bottom Layer w10: v2(-2922.27,-575.43) JP2.14
P3.4: JP2.15 U1.56 | length 2047.1
  Top Layer w7: v2(-2922.27,-525.43) -2903.77,-506.93 -2903.77,-475.23 -2739.47,-310.93 -2649.22,-310.93 -2517.91,-442.24 -2070.14,-442.24 -1926.09,-586.3 -1926.09,-1135.24 -2050.33,-1259.49 U1.56
  Bottom Layer w10: v2(-2922.27,-525.43) JP2.15
P3.5: JP2.16 U1.55 | length 2057.9
  Top Layer w7: v2(-2922.27,-475.43) -2922.27,-475.34 -2744.86,-297.93 -2643.84,-297.93 -2512.53,-429.24 -2064.76,-429.24 -1913.09,-580.91 -1913.09,-1141.24 -2047.08,-1275.24 U1.55
  Bottom Layer w10: v2(-2922.27,-475.43) JP2.16
P3.6: JP2.17
P3.7: JP2.18
REGI: C10.1 C13.1 C21.1 JP2.10 L3.1 R1.1 SW1.2 U1.27 | length 5717.4
  Top Layer w7: U1.27 -2407.31,-1537.02 -2368.09,-1576.24 -2368.09,-1636.43 v2(-2359.09,-1645.43) C13.1
  Top Layer w10: R1.1 -2942.65,-272 -2774,-272 v2@-2731,-229 ; L3.1 -2589.53,-1527.47 -2575,-1542 -2575,-1707 -2631.87,-1763.87 -2632.37,-1763.87 -2655,-1786.5 -2655,-1934 -2588,-2001 v3(-2023,-2001)
  Top Layer w12: C10.1@-2660.17,-212.24 -2636.76,-212.24 -2490.76,-358.24 -1950.09,-358.24 -1871.09,-437.24 -1871.09,-1141.24 v2(-1865.09,-1147.24)
  Top Layer w18: C21.1 L3.1@-2620,-1527.55
  Top Layer w20: v2@-2729,-231 -2701,-203 C10.1
  Bottom Layer w18: v2(-2359.09,-1645.43) -2359.09,-1645.82 -2148.33,-1856.58 -1643.79,-1856.58 -1486.09,-1698.87 -1486.09,-1278.93 -1617.78,-1147.24 v2(-1865.09,-1147.24) ; SW1.2 -2024,-1858.58
  Bottom Layer w20: v2(-2729,-230) -2729,-274.02 JP2.10
REGO: C14.1 U1.31 | length 176.1
  Top Layer w7: U1.31 -2344.32,-1524.01 -2277.09,-1591.24 C14.1
RESETN: C3.1 JP2.19 R1.2 U1.85 | length 1217.5
  Top Layer w7: C3.1 -2978.09,-385.43 -2978.09,-733.22 -2742.06,-969.24 -2481.65,-969.24 -2423.06,-1027.83 U1.85
  Top Layer w10: C3.1 R1.2 v1(-2936,-325.43)
  Bottom Layer w10: v1(-2936,-325.43) JP2.19
RFI: C4.1 U1.20 | length 78.1
  Top Layer w8: C4.1@-2579.87,-1401.22 U1.20
RFO: C17.1 C20.1 L3.2 U1.21 | length 195
  Top Layer w8: C17.1@-2580.31,-1487.24 C17.1 ; C17.1 -2536.09,-1443.47 -2536.09,-1429.24 -2523.81,-1416.97 U1.21
  Top Layer w25: C20.1 C17.1@-2580.31,-1487.24
RTCI: C2.1 U1.54 Y2.1 | length 197.6
  Top Layer w7: U1.54 C2.1@-1971.83,-1290.98 ; C2.1 -1940.94,-1283.24 Y2.1
RTCO: C1.1 U1.53 Y2.2 | length 418.4
  Top Layer w7: U1.53 -1851.73,-1306.73 -1815.51,-1270.51 Y2.2 -1815.51,-1229.82 C1.1
S0.0: J2.9 U1.3 | length 1375.6
  Top Layer w7: v2(-3050.09,-283.39) -3050.09,-753.14 -2794.23,-1009 -2650.33,-1009 -2525.83,-1133.5 U1.3
  Bottom Layer w7: J2.9 v2(-3050.09,-283.39)
S0.1: J2.10 U1.9 | length 1517.7
  Top Layer w7: v2(-3101.09,-232.61) -3117,-248.53 -3117,-784 -2827,-1074 -2699.33,-1074 -2545.34,-1227.99 U1.9
  Bottom Layer w7: J2.10 -3222.13,-232.61 v2(-3101.09,-232.61)
S0.2: J2.11 U1.10 | length 1564.3
  Top Layer w7: v2(-3120.09,-213.61) -3132,-225.53 -3132,-787.38 -2832.38,-1087 -2705.33,-1087 -2548.59,-1243.74 U1.10
  Bottom Layer w7: J2.11@-3250.09,-125.91 -3162.39,-213.61 v2(-3120.09,-213.61)
S0.3: J2.12 U1.11 | length 1631
  Top Layer w7: v2(-3139.09,-194.61) -3145,-200.53 -3145,-792.77 -2837.77,-1100 -2711.33,-1100 -2646.83,-1164.5 -2551.84,-1259.49 U1.11
  Bottom Layer w7: J2.12 -3162,-135.25 -3162,-154.36 -3162.59,-154.95 -3162.59,-171.11 v2(-3139.09,-194.61)
S0.4: J3.1 U1.12 | length 1611.5
  Top Layer w7: v2(-3144.09,-162.61) -3158.09,-176.61 -3158.09,-798.07 -2843.15,-1113 -2717.33,-1113 -2659.83,-1170.5 -2555.1,-1275.24 U1.12
  Bottom Layer w7: v2(-3144.09,-162.61) J3.1@-3144.09,-46.31
S0.5: J3.2 U1.13 | length 1723
  Top Layer w7: v2(-3065.09,-142.61) -3150.25,-142.61 -3171.09,-163.45 -3171.09,-803.45 -2848.54,-1126 -2723.33,-1126 -2568.1,-1281.24 -2568.1,-1282.67 -2559.78,-1290.98 U1.13
  Bottom Layer w7: v2@-3065.35,-142.61 J3.2@-3065.35,-46.32
S0.6: J3.3 U1.14 | length 1829.3
  Top Layer w7: v2@-2986.09,-123.61 v2(-2986.61,-123.61) -3149.63,-123.61 -3184.09,-158.07 -3184.09,-808.84 -2853.92,-1139 -2729.33,-1139 -2581.1,-1287.24 -2581.1,-1288.06 -2562.42,-1306.73 U1.14
  Bottom Layer w7: v2(-2986.61,-123.61) J3.3@-2986.61,-46.31
S0.7: J3.4 U1.15 | length 1901.6
  Top Layer w7: J3.4@-2907.87,-46.31 -2966.17,-104.61 -3149.02,-104.61 -3198.09,-153.68 -3198.09,-813.22 -2859.31,-1152 -2735.33,-1152 -2594.1,-1293.24 -2594.1,-1293.44 -2565.06,-1322.48 U1.15
S1.0: J3.5 U1.48 | length 2586
  Top Layer w7: J3.5@-2829.13,-46.32 -2788.2,-87.24 -2731.09,-87.24 -2690.33,-128 -2508.33,-128 -2327.09,-309.24 -1902.76,-309.24 -1837,-375 -1837,-897.77 -1681,-1053.77 -1681,-1309.54 -1756.93,-1385.47 U1.48
S1.1: J3.6 U1.47 | length 2546.1
  Top Layer w7: J3.6@-2750.39,-46.31 -2681.7,-115 -2502.33,-115 -2321.09,-296.24 -1897.37,-296.24 -1824,-369.62 -1824,-892.39 -1668,-1048.39 -1668,-1314.92 -1754.3,-1401.22 U1.47
S1.2: J3.7 U1.46 | length 2506.2
  Top Layer w7: J3.7@-2671.65,-46.31 -2615.96,-102 -2496.33,-102 -2315.09,-283.24 -1891.99,-283.24 -1811,-364.23 -1811,-887 -1655,-1043 -1655,-1320.31 -1751.66,-1416.97 U1.46
S1.3: J3.8 U1.45 | length 2466.3
  Top Layer w7: J3.8@-2592.91,-46.31 -2550.22,-89 -2490.33,-89 -2309.09,-270.24 -1886.6,-270.24 -1798,-358.85 -1798,-881.62 -1642,-1037.62 -1642,-1325.69 -1749.02,-1432.72 U1.45
S1.4: J3.9 U1.44 | length 2510
  Top Layer w7: J3.9@-2514.17,-46.32 -2303.24,-257.24 -1881.22,-257.24 -1785,-353.46 -1785,-876.23 -1603,-1058.23 -1603,-1337 -1743.24,-1477.24 U1.44@-2139.56,-1477.24
S1.5: J3.10 U1.43 | length 2509.3
  Top Layer w7: J3.10@-2435.43,-46.31 -2237.5,-244.24 -1875.83,-244.24 -1772,-348.08 -1772,-870.85 -1590,-1052.85 -1590,-1342.38 -1739.86,-1492.24 -2148.09,-1492.24 -2155.34,-1484.99 U1.43
S1.6: J3.11 U1.42 | length 2491.3
  Top Layer w7: J3.11@-2356.68,-46.31 -2171.76,-231.24 -1870.45,-231.24 -1759,-342.69 -1759,-865.46 -1577,-1047.46 -1577,-1347.77 -1734.47,-1505.24 -2154.09,-1505.24 -2171.09,-1488.24 U1.42
S1.7: J3.12 U1.41 | length 2473.3
  Top Layer w7: J3.12@-2277.94,-46.32 -2106.02,-218.24 -1865.06,-218.24 -1746,-337.31 -1746,-860.08 -1564,-1042.08 -1564,-1353.15 -1729.09,-1518.24 -2160.09,-1518.24 -2186.84,-1491.5 U1.41
S2.0: J3.13 U1.40 | length 2455.3
  Top Layer w7: U1.40 -2202.58,-1494.75 -2166.09,-1531.24 -1723.71,-1531.24 -1551,-1358.54 -1551,-1036.69 -1733,-854.69 -1733,-331.92 -1859.68,-205.24 -2040.28,-205.24 J3.13@-2199.2,-46.31
S2.1: J3.14 U1.39 | length 2437.3
  Top Layer w7: U1.39 -2218.33,-1498 -2172.09,-1544.24 -1718.32,-1544.24 -1538,-1363.92 -1538,-1031.31 -1720,-849.31 -1720,-326.54 -1944.54,-102 -2064.78,-102 J3.14@-2120.46,-46.32
S2.2: J3.15 U1.38 | length 2419.4
  Top Layer w7: U1.38 -2234.08,-1501.25 -2178.09,-1557.24 -1712.94,-1557.24 -1525,-1369.31 -1525,-1025.92 -1707,-843.92 -1707,-321 -1939,-89 -1999.04,-89 J3.15@-2041.72,-46.31
S2.3: J3.16 U1.37 | length 2401.5
  Top Layer w7: U1.37 -2249.83,-1504.5 -2184.09,-1570.24 -1707.55,-1570.24 -1512,-1374.69 -1512,-1020.54 -1694,-838.54 -1694,-315.3 J3.16@-1962.98,-46.31
S2.4: J3.17 U1.36 | length 2418.9
  Top Layer w7: U1.36 -2265.58,-1507.76 -2190.09,-1583.24 -1702.17,-1583.24 -1499,-1380.08 -1499,-1015.15 -1679,-835.15 -1679,-251.56 J3.17@-1884.24,-46.31
S2.5: J3.18 U1.35 | length 2436.2
  Top Layer w7: U1.35 -2281.32,-1511.01 -2196.09,-1596.24 -1696.78,-1596.24 -1486,-1385.46 -1486,-1009.77 -1666,-829.77 -1666,-244 -1805.5,-104.5 J3.18@-1805.5,-46.32
S2.6: J3.19 U1.34 | length 2465.3
  Top Layer w7: U1.34 -2297.07,-1514.26 -2202.09,-1609.24 -1691.4,-1609.24 -1473,-1390.85 -1473,-1004.38 -1653,-824.38 -1653,-100 -1706.68,-46.31 J3.19@-1726.76,-46.31
S2.7: J3.20 U1.33 | length 2467.4
  Top Layer w7: U1.33 -2312.82,-1517.51 -2208.09,-1622.24 -1686.01,-1622.24 -1460,-1396.23 -1460,-999 -1640,-819 -1640,-66.46 J3.20@-1654.09,-52.38
S3.0: J3.21 U1.52 | length 1967.1
  Top Layer w7: U1.52 -1767.48,-1322.48 -1755,-1310 -1755,-1120.55 -1774,-1101.55 v1(-1774,-1096)
  Bottom Layer w7: v1(-1774,-1096) -1774,-1072.84 -1731.16,-1030 -1579.15,-1030 -1372.06,-822.91 -1372.06,-243.53 J3.21
S3.1: J3.22 U1.51 | length 1956.7
  Top Layer w7: U1.51 -1764.84,-1338.23 -1742,-1315.38 -1742,-1115.16 -1755,-1102.16 v1(-1755,-1080)
  Bottom Layer w7: v1(-1755,-1080) -1755,-1073.62 -1724.38,-1043 -1573.77,-1043 -1359.06,-828.29 -1359.06,-177.79 J3.22
S3.2: J3.23 U1.50 | length 1946.4
  Top Layer w7: U1.50 -1762.21,-1353.98 -1729,-1320.77 -1729,-1102 v1(-1735,-1096)
  Bottom Layer w7: v1(-1735,-1096) -1735,-1072 -1719,-1056 -1568.38,-1056 -1346.06,-833.68 -1346.06,-112.05 J3.23
S3.3: J3.24 U1.49 | length 1931.8
  Top Layer w7: U1.49 -1759.57,-1369.72 -1716,-1326.15 v1(-1716,-1080)
  Bottom Layer w7: v1(-1716,-1080) -1705,-1069 -1563,-1069 -1333.06,-839.06 J3.24
S3.4: U1.87
S3.5: U1.88
S3.6: U1.1
S3.7: U1.2
S4.0: U1.86
S4.1: U1.4
S4.2: U1.5
S4.3: U1.6
S4.4: U1.7
S4.5: U1.8
TRX: C23.2 J1.1 | length 73
  Top Layer w39: J1.1 C23.2@-3179.09,-1487.24
VDD_A: C8.1 U1.19 | length 140
  Top Layer w7: C8.1 -2609.09,-1354.24 -2577.86,-1385.47 U1.19
VDD_D: R2.2 U1.17 | length 202.3
  Top Layer w7: R2.2 -2651.09,-1274.24 -2571.35,-1353.98 U1.17
VDD_P: C12.2 C22.2 C25.1 U1.22 U1.26 | length 1374.3
  Top Layer w8: U1.22@-2511,-1433 -2511,-1447 -2535,-1471 -2535,-1498 -2510.09,-1522.91 -2510.09,-1724.72 -2604.24,-1818.87 -2604.24,-1901.87 -2558.24,-1947.87 -2335.09,-1947.87 -2289.09,-1901.87 -2289.09,-1818.87 -2382.09,-1725.87 -2382.09,-1601.24 C12.2@-2403.09,-1580.24 ; U1.26 -2423.06,-1559.27 C12.2@-2402.59,-1579.74
VDD_S: C6.1 U1.16 | length 233.4
  Top Layer w7: C6.1 -2672.09,-1234.24 -2568.1,-1338.23 U1.16
XI: U1.24 U2.1 Y1.2 | length 446.1
  Top Layer w8: Y1.2 -2500.67,-1850.22 U2.1 -2494.84,-1788.5 -2454.55,-1748.21 U1.24
XO: U1.25 U2.3 Y1.1 | length 457.8
  Top Layer w8: U1.25 -2438.8,-1748.21 -2398.52,-1788.5 U2.3 -2357.54,-1856.08 Y1.1
pads on no net: JP1. JP1.9 JP1.10 JP1.19 JP2. JP2.9 SW1. SW1.3 U1.

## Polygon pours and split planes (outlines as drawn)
GND on Top Layer "TopLayer-No Net" (solid, remove dead copper, pour order 4): -3307.09,-2401.57 0,-2401.57 0,0 -3307.09,0
GND on Bottom Layer "TopLayer-No Net" (solid, remove dead copper, pour order 3): -3307.09,-2397.87 0,-2397.87 0,0 -3307.09,0

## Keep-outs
Keep-Out Layer:
  the board outline again, w8

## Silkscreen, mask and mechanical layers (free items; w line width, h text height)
Top Overlay:
  text "S0.4" at -3129.09,28.69 h30 r90
  text "S0.5" at -3050.35,28.69 h30 r90
  text "S0.6" at -2971.61,28.69 h30 r90
  text "S0.7" at -2892.87,28.69 h30 r90
  text "S1.0" at -2814.13,28.69 h30 r90
  text "S1.1" at -2735.39,28.69 h30 r90
  text "S1.2" at -2656.65,28.69 h30 r90
  text "S1.3" at -2577.91,28.69 h30 r90
  text "S1.4" at -2499.17,28.69 h30 r90
  text "S1.5" at -2420.43,28.69 h30 r90
  text "S1.6" at -2341.69,28.69 h30 r90
  text "S1.7" at -2262.95,28.69 h30 r90
  text "S2.0" at -2184.2,28.69 h30 r90
  text "S2.1" at -2105.46,28.69 h30 r90
  text "S2.2" at -2026.72,28.69 h30 r90
  text "S2.3" at -1947.98,28.69 h30 r90
  text "S2.4" at -1869.24,28.69 h30 r90
  text "S2.5" at -1790.5,28.69 h30 r90
  text "S2.6" at -1711.76,28.69 h30 r90
  text "S2.7" at -1633.02,28.69 h30 r90
  text "S3.0" at -1554.28,28.69 h30 r90
  text "S3.1" at -1475.54,28.69 h30 r90
  text "S3.2" at -1396.8,28.69 h30 r90
  text "S3.3" at -1318.06,28.69 h30 r90
  text "S0.2" at -3525.09,-140.91 h30
  text "S0.1" at -3525.09,-219.65 h30
  text "S0.0" at -3525.09,-298.39 h30
  text "P2.7/S3" at -3525.09,-377.13 h30
  text "P2.6/S2" at -3525.09,-455.87 h30
  text "P2.5/S1" at -3525.09,-534.61 h30
  text "P2.4/S0" at -3525.09,-613.35 h30
  text "P2.3/C3" at -3525.09,-692.1 h30
  text "P2.2/C2" at -3525.09,-770.84 h30
  text "P2.1/C1" at -3525.09,-849.58 h30
  text "P2.0/C0" at -3525.09,-928.32 h30
  text "AMICCOM" at -1264.09,-2047.87 h100
  text "HWD9508F4-A90-02" at -1264.09,-2160.87 h80
  text "ON" at -2370,-2348 h60
  text "OFF" at -1776,-2351 h60
Bottom Overlay:
  lines w6: -7.87,0 -7.87,-2283.46 -1259.84,-2283.46 -1259.84,0 0,0
  text "-" at -830,-2397 h100
  text "+" at -520,-2397 h100
Bottom Solder:
  rectangle: -2730.8,-1892.44 -2676.8,-1806.44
